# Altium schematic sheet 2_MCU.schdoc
size 309 x 223 mm; Symbol: Artery_A4; Device: Artery_A4; Company: Artery Technology; Drawed: SD; Version: 1.2; Page Size: A4; @Project Name: AT_START_F403A_V1.2; @Page Count: 4; @Update Date: 2023-09-07; @Create Date: 2023-08-15; @Schematic Name: AT_START_F403A; @Page No: 2; @Page Name: MCU
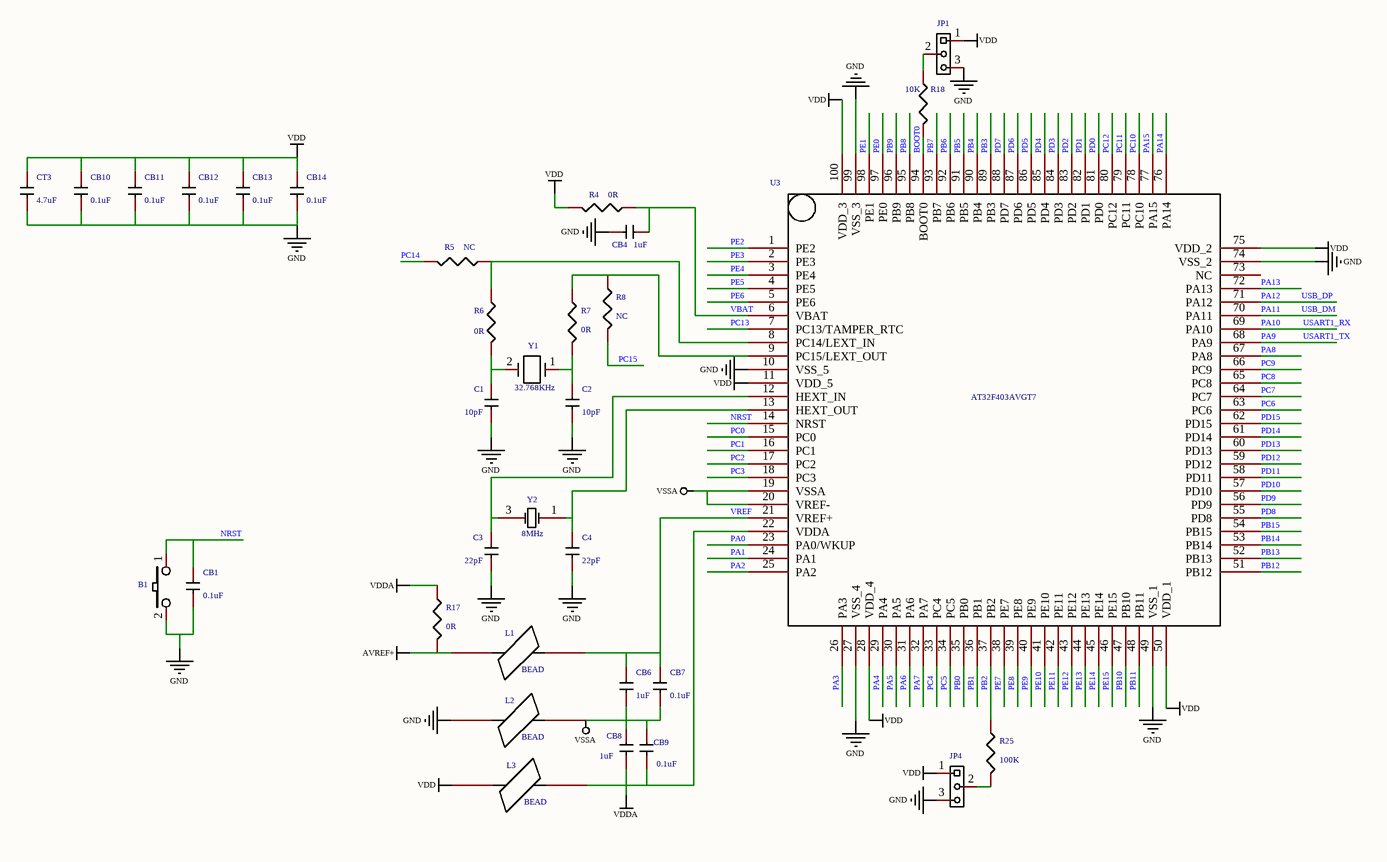
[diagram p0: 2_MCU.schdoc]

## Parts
B1  PB,BLACK,SMD_2P  [KEY_SOP_6*6]  (value not drawn)
C1  10pF  [C0603]
C2  10pF  [C0603]
C3  22pF  [C0603]
C4  22pF  [C0603]
CB1  0.1uF  [C0603]
CB4  1uF  [C0603]
CB6  1uF  [C0603]
CB7  0.1uF  [C0603]
CB8  1uF  [C0603]
CB9  0.1uF  [C0603]
CB10  0.1uF  [C0603]
CB11  0.1uF  [C0603]
CB12  0.1uF  [C0603]
CB13  0.1uF  [C0603]
CB14  0.1uF  [C0603]
CT3  4.7uF  [C0603]
JP1  1X3P_2.54M  [HDR1X3]  (value not drawn)
JP4  1X3P_2.54M  [HDR1X3]  (value not drawn)
L1  BEAD  [r0603]
L2  BEAD  [r0603]
L3  BEAD  [r0603]
R4  0R  [SB-PAD]
R5  NC  [SB-PAD]
R6  0R  [SB-PAD]
R7  0R  [SB-PAD]
R8  NC  [SB-PAD]
R17  0R  [SB-PAD]
R18  10K  [r0603]
R25  100K  [r0603]
U3  AT32F403AVGT7  [LQFP100_14*14]
Y1  32.768KHz  [XTAL_SOP - FC-12M]
Y2  8MHz  [SMD_5032_4P]

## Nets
AVREF+: L1.1 R17.2
GND: B1.2 C1.2 C2.2 C3.2 C4.2 CB1.2 CB4.2 CB10.2 CB11.2 CB12.2 CB13.2 CB14.2 CT3.2 JP1.3 JP4.3 L2.1 U3.10(VSS_5) U3.27(VSS_4) U3.49(VSS_1) U3.74(VSS_2) U3.99(VSS_3)
VDD: CB10.1 CB11.1 CB12.1 CB13.1 CB14.1 CT3.1 JP1.1 JP4.1 L3.1 R4.2 U3.11(VDD_5) U3.28(VDD_4) U3.50(VDD_1) U3.75(VDD_2) U3.100(VDD_3)
VDDA: CB8.2 CB9.2 L3.2 R17.1 U3.22(VDDA)
VSSA: CB6.2 CB7.2 CB8.1 CB9.1 L2.2 U3.19(VSSA) U3.20(VREF-)
BOOT0: R18.2 U3.94(BOOT0)
NRST: B1.1 CB1.1 U3.14(NRST)
PA0: U3.23(PA0/WKUP)
PA1: U3.24(PA1)
PA2: U3.25(PA2)
PA3: U3.26(PA3)
PA4: U3.29(PA4)
PA5: U3.30(PA5)
PA6: U3.31(PA6)
PA7: U3.32(PA7)
PA8: U3.67(PA8)
PA9: U3.68(PA9)  [also labelled USART1_TX]
PA10: U3.69(PA10)  [also labelled USART1_RX]
PA11: U3.70(PA11)  [also labelled USB_DM]
PA12: U3.71(PA12)  [also labelled USB_DP]
PA13: U3.72(PA13)
PA14: U3.76(PA14)
PA15: U3.77(PA15)
PB0: U3.35(PB0)
PB1: U3.36(PB1)
PB2: R25.1 U3.37(PB2)
PB3: U3.89(PB3)
PB4: U3.90(PB4)
PB5: U3.91(PB5)
PB6: U3.92(PB6)
PB7: U3.93(PB7)
PB8: U3.95(PB8)
PB9: U3.96(PB9)
PB10: U3.47(PB10)
PB11: U3.48(PB11)
PB12: U3.51(PB12)
PB13: U3.52(PB13)
PB14: U3.53(PB14)
PB15: U3.54(PB15)
PC0: U3.15(PC0)
PC1: U3.16(PC1)
PC2: U3.17(PC2)
PC3: U3.18(PC3)
PC4: U3.33(PC4)
PC5: U3.34(PC5)
PC6: U3.63(PC6)
PC7: U3.64(PC7)
PC8: U3.65(PC8)
PC9: U3.66(PC9)
PC10: U3.78(PC10)
PC11: U3.79(PC11)
PC12: U3.80(PC12)
PC13: U3.7(PC13/TAMPER_RTC)
PC14: R5.2
PC15: R8.2
PD0: U3.81(PD0)
PD1: U3.82(PD1)
PD2: U3.83(PD2)
PD3: U3.84(PD3)
PD4: U3.85(PD4)
PD5: U3.86(PD5)
PD6: U3.87(PD6)
PD7: U3.88(PD7)
PD8: U3.55(PD8)
PD9: U3.56(PD9)
PD10: U3.57(PD10)
PD11: U3.58(PD11)
PD12: U3.59(PD12)
PD13: U3.60(PD13)
PD14: U3.61(PD14)
PD15: U3.62(PD15)
PE0: U3.97(PE0)
PE1: U3.98(PE1)
PE2: U3.1(PE2)
PE3: U3.2(PE3)
PE4: U3.3(PE4)
PE5: U3.4(PE5)
PE6: U3.5(PE6)
PE7: U3.38(PE7)
PE8: U3.39(PE8)
PE9: U3.40(PE9)
PE10: U3.41(PE10)
PE11: U3.42(PE11)
PE12: U3.43(PE12)
PE13: U3.44(PE13)
PE14: U3.45(PE14)
PE15: U3.46(PE15)
VBAT: CB4.1 R4.1 U3.6(VBAT)
VREF: CB6.1 CB7.1 L1.2 U3.21(VREF+)
NetC1_1: C1.1 R6.2 Y1.2
NetC2_1: C2.1 R7.2 Y1.1
NetC3_1: C3.1 U3.12(HEXT_IN) Y2.3(OSC2)
NetC4_1: C4.1 U3.13(HEXT_OUT) Y2.1(OSC1)
NetJP1_2: JP1.2 R18.1
NetJP4_2: JP4.2 R25.2
NetR5_1: R5.1 R6.1 U3.8(PC14/LEXT_IN)
NetR7_1: R7.1 R8.1 U3.9(PC15/LEXT_OUT)

Not connected (* = marked no-connect by the designer): U3 73(NC)

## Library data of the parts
B1 = PB,BLACK,SMD_2P: Symbol: Push_Bottom,Blue,SMD_2P; Add into BOM: yes
C1 C2 = 10pF: Symbol: 10pF,50V,5%,SMD0603; Add into BOM: yes
C3 C4 = 22pF: Symbol: 10pF,50V,5%,SMD0603; Add into BOM: yes
CB1 CB7 CB9 = 0.1uF: Symbol: 0.1uF,50V,20%,SMD0603; Add into BOM: yes
CB4 CB6 CB8 = 1uF: Symbol: 0.1uF,50V,20%,SMD0603; Add into BOM: yes
CB10-CB14 = 0.1uF: Symbol: 0.1uF,25V,20%,SMD0402; Add into BOM: yes
CT3 = 4.7uF: Symbol: 0.1uF,25V,20%,SMD0402; Add into BOM: yes
JP1 JP4 = 1X3P_2.54M: Symbol: 1X3P,Male,DIP_2.54; Add into BOM: yes
L1-L3 = BEAD: Add into BOM: yes
R4 R17 = 0R: Symbol: 470,1/10W,1%,SMD0603; Add into BOM: yes
R5 R8 = NC: Symbol: 0,1/10W,1%,SMD0603; Add into BOM: yes
R6 R7 = 0R: Symbol: 0,1/10W,1%,SMD0603; Add into BOM: yes
R18 = 10K: Symbol: 10K,1/10W,1%,SMD0603; Add into BOM: yes
R25 = 100K: Symbol: 10K,1/10W,1%,SMD0603; Add into BOM: yes
U3 = AT32F403AVGT7: Symbol: LQFP100; Add into BOM: yes
Y1 = 32.768KHz: FC-12M 2012 EPSON; Symbol: 32.768KHz,CRY,30PPM,Size_3X8; Add into BOM: yes
Y2 = 8MHz: ?片晶振; Symbol: SMD-5032_4P  8MHZ 20PF 10PPM; Add into BOM: yes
